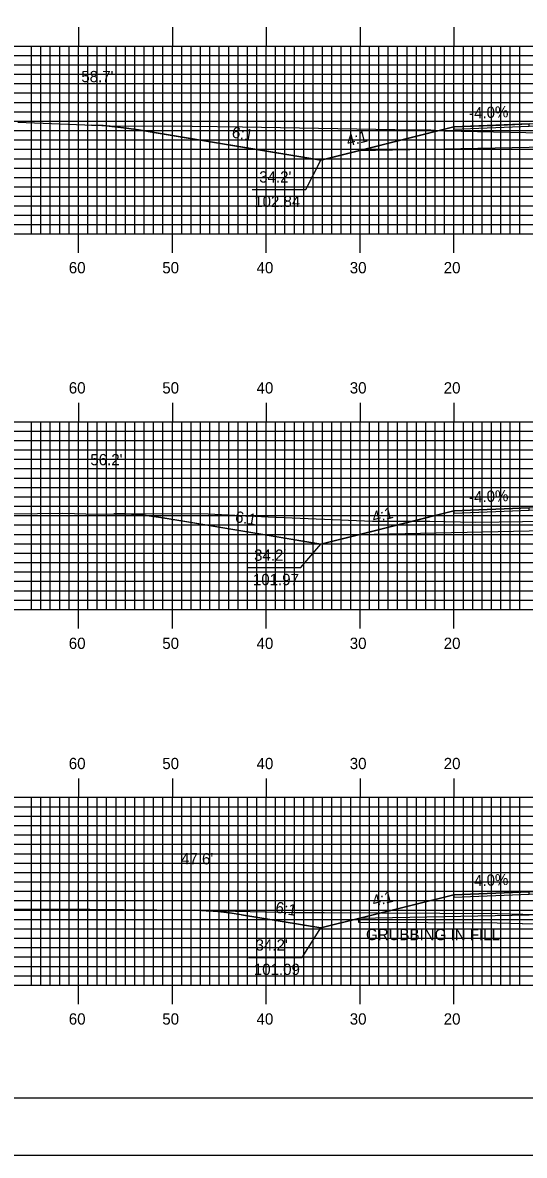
# Model space of a CAD drawing. Extents: x 1779106 to 1779449, y 442591 to 442811.
# Drawn here: x 1779205.4 to 1779258.8, y 442590.5 to 442711.2 of the extents above; entities that cross this region are included whole.
import ezdxf

# ---------------------------------------------------------------- set-up
doc = ezdxf.new("R2010")
doc.units = 0
for name, color, linetype in [('ANNOTATION', 7, 'Continuous'), ('BORDER', 7, 'Continuous'), ('D_Roadway_Centerline', 7, 'Continuous'), ('D_Roadway_Edge_Shoulder', 7, 'Continuous'), ('D_Roadway_SlopeLines', 7, 'Continuous'), ('D_Roadway_SubGrade', 7, 'Continuous'), ('D_Text_Standard', 7, 'Continuous'), ('GRUBBING IN FILL', 7, 'Continuous'), ('H_V ANNOTATION', 7, 'Continuous'), ('MAJOR', 7, 'Continuous'), ('MINOR', 7, 'Continuous'), ('PLOT BOUNDARY', 7, 'Continuous'), ('S_Roadway_Centerline', 7, 'Continuous')]:
    doc.layers.add(name, color=color, linetype=linetype)

msp = doc.modelspace()

# ---------------------------------------------------------------- linework, layer by layer
at = {"layer": 'ANNOTATION'}
for points in [[(1779229.85, 442693.4), (1779235.54, 442693.4), (1779237.16, 442696.51)], [(1779229.3, 442653.13), (1779235, 442653.13), (1779237.16, 442655.63)], [(1779229.46, 442611.62), (1779235.15, 442611.62), (1779237.16, 442614.76)]]:
    msp.add_lwpolyline(points, dxfattribs=at)
at = {"layer": 'BORDER'}
msp.add_lwpolyline([(1779121.73, 442596.67), (1779441.73, 442596.67), (1779441.73, 442806.67), (1779121.73, 442806.67)], close=True, dxfattribs=at)
at = {"layer": 'D_Roadway_Centerline'}
for points in [[(1779212.71, 442700.25), (1779213.96, 442700.19), (1779215.21, 442700.08), (1779216.46, 442699.94), (1779217.71, 442699.75), (1779219.39, 442699.47), (1779237.16, 442696.51), (1779237.6, 442696.62), (1779241.15, 442697.51), (1779251.33, 442700.05), (1779255.5, 442700.22), (1779259.33, 442700.37), (1779269.01, 442700.57), (1779271.33, 442700.61), (1779283.33, 442700.37), (1779289, 442700.15), (1779296.66, 442699.84), (1779306.37, 442697.41)], [(1779215.1, 442658.85), (1779216.35, 442658.84), (1779217.6, 442658.78), (1779217.76, 442658.76), (1779218.85, 442658.66), (1779220.1, 442658.48), (1779222.99, 442658), (1779237.16, 442655.63), (1779241.15, 442656.63), (1779251.33, 442659.18), (1779259.33, 442659.5), (1779271.33, 442659.74), (1779283.33, 442659.5), (1779300, 442658.83), (1779307.08, 442657.06), (1779309.41, 442656.48)], [(1779223.68, 442616.65), (1779224.43, 442616.61), (1779224.94, 442616.59), (1779225.68, 442616.54), (1779226.18, 442616.5), (1779227.43, 442616.36), (1779228.62, 442616.18), (1779228.69, 442616.17), (1779237.16, 442614.76), (1779241.16, 442615.76), (1779251.33, 442618.3), (1779259.33, 442618.62), (1779271.33, 442618.86), (1779271.33, 442618.86), (1779276.97, 442618.75), (1779283.33, 442618.62), (1779289.1, 442618.39), (1779303.33, 442617.82)]]:
    msp.add_lwpolyline(points, dxfattribs=at)
at = {"layer": 'D_Roadway_Edge_Shoulder'}
for points in [[(1779259.33, 442700.37), (1779251.33, 442700.05), (1779251.33, 442699.8), (1779259.33, 442700.12)], [(1779259.33, 442659.5), (1779251.33, 442659.18), (1779251.33, 442658.93), (1779259.33, 442659.25)], [(1779259.33, 442618.62), (1779251.33, 442618.3), (1779251.33, 442618.05), (1779259.33, 442618.37)]]:
    msp.add_lwpolyline(points, close=True, dxfattribs=at)
at = {"layer": 'D_Roadway_SlopeLines'}
for points in [[(1779237.16, 442696.51), (1779217.71, 442699.75), (1779216.46, 442699.94), (1779215.21, 442700.08), (1779213.96, 442700.19), (1779212.71, 442700.25)], [(1779251.33, 442700.05), (1779237.16, 442696.51)], [(1779237.16, 442655.63), (1779220.1, 442658.48), (1779218.85, 442658.66), (1779217.6, 442658.78), (1779216.35, 442658.84), (1779215.1, 442658.85)], [(1779251.33, 442659.18), (1779237.16, 442655.63)], [(1779251.33, 442618.3), (1779237.16, 442614.76)], [(1779237.16, 442614.76), (1779228.69, 442616.17), (1779227.43, 442616.36), (1779226.18, 442616.5), (1779224.94, 442616.59), (1779223.68, 442616.65)]]:
    msp.add_lwpolyline(points, dxfattribs=at)
at = {"layer": 'D_Roadway_SubGrade'}
for points in [[(1779259.33, 442697.87), (1779241.15, 442697.51), (1779251.33, 442700.05), (1779251.33, 442699.8), (1779259.33, 442700.12), (1779271.33, 442700.36), (1779283.33, 442700.12), (1779296.66, 442699.59), (1779296.66, 442699.84), (1779306.37, 442697.41), (1779283.33, 442697.87), (1779271.33, 442698.11)], [(1779259.33, 442657), (1779241.15, 442656.63), (1779251.33, 442659.18), (1779251.33, 442658.93), (1779259.33, 442659.25), (1779271.33, 442659.49), (1779283.33, 442659.25), (1779300, 442658.58), (1779300, 442658.83), (1779309.41, 442656.48), (1779283.33, 442657), (1779271.33, 442657.24)], [(1779259.33, 442616.12), (1779241.16, 442615.76), (1779251.33, 442618.3), (1779251.33, 442618.05), (1779259.33, 442618.37), (1779271.33, 442618.61), (1779283.33, 442618.37), (1779303.33, 442617.57), (1779303.33, 442617.82), (1779312.46, 442615.54), (1779283.33, 442616.12), (1779271.33, 442616.36)]]:
    msp.add_lwpolyline(points, close=True, dxfattribs=at)
at = {"layer": 'GRUBBING IN FILL'}
msp.add_line((1779241.16, 442615.76), (1779241.16, 442615.37), dxfattribs=at)
msp.add_line((1779241.16, 442615.76), (1779241.16, 442615.37), dxfattribs=at)
msp.add_lwpolyline([(1779241.16, 442615.76), (1779241.16, 442615.37), (1779248.55, 442615.34), (1779255.95, 442615.31), (1779259.9, 442615.21), (1779270.16, 442614.86), (1779271.33, 442614.86), (1779271.33, 442615.86), (1779270.18, 442615.86), (1779265.69, 442616.03), (1779261.74, 442616.17), (1779259.33, 442616.12), (1779250.24, 442615.94)], close=True, dxfattribs=at)
msp.add_lwpolyline([(1779241.16, 442615.76), (1779241.16, 442615.37), (1779248.55, 442615.34), (1779255.95, 442615.31), (1779259.9, 442615.21), (1779270.16, 442614.86), (1779271.33, 442614.86), (1779271.33, 442615.86), (1779270.18, 442615.86), (1779265.69, 442616.03), (1779261.74, 442616.17), (1779259.33, 442616.12), (1779250.24, 442615.94)], close=True, dxfattribs=at)
msp.add_lwpolyline([(1779241.16, 442615.37), (1779255.95, 442615.31), (1779258.64, 442615.23), (1779261.17, 442615.19), (1779270.16, 442614.86), (1779280.39, 442614.79), (1779284.94, 442614.75), (1779301.5, 442614.5)], dxfattribs=at)
msp.add_lwpolyline([(1779241.16, 442615.37), (1779255.95, 442615.31), (1779258.64, 442615.23), (1779261.17, 442615.19), (1779270.16, 442614.86), (1779280.39, 442614.79), (1779284.94, 442614.75), (1779301.5, 442614.5)], dxfattribs=at)
at = {"layer": 'MAJOR'}
for p, q in [((1779211.33, 442710.67), (1779211.33, 442708.67)), ((1779221.33, 442710.67), (1779221.33, 442708.67)), ((1779231.33, 442710.67), (1779231.33, 442708.67)), ((1779241.33, 442710.67), (1779241.33, 442708.67)), ((1779251.33, 442710.67), (1779251.33, 442708.67)), ((1779131.33, 442708.67), (1779411.33, 442708.67)), ((1779131.33, 442708.67), (1779411.33, 442708.67)), ((1779211.33, 442688.67), (1779211.33, 442708.67)), ((1779221.33, 442688.67), (1779221.33, 442708.67)), ((1779231.33, 442688.67), (1779231.33, 442708.67)), ((1779241.33, 442688.67), (1779241.33, 442708.67)), ((1779251.33, 442688.67), (1779251.33, 442708.67)), ((1779131.33, 442703.67), (1779411.33, 442703.67)), ((1779131.96, 442698.67), (1779411.96, 442698.67)), ((1779131.33, 442693.67), (1779411.33, 442693.67)), ((1779131.33, 442688.67), (1779411.33, 442688.67)), ((1779131.33, 442688.67), (1779411.33, 442688.67)), ((1779211.33, 442686.66), (1779211.33, 442688.67)), ((1779221.33, 442686.66), (1779221.33, 442688.67)), ((1779231.33, 442686.66), (1779231.33, 442688.67)), ((1779241.33, 442686.66), (1779241.33, 442688.67)), ((1779251.33, 442686.66), (1779251.33, 442688.67)), ((1779211.33, 442670.67), (1779211.33, 442668.67)), ((1779221.33, 442670.67), (1779221.33, 442668.67)), ((1779231.33, 442670.67), (1779231.33, 442668.67)), ((1779241.33, 442670.67), (1779241.33, 442668.67)), ((1779251.33, 442670.67), (1779251.33, 442668.67)), ((1779131.33, 442668.67), (1779411.33, 442668.67)), ((1779131.33, 442668.67), (1779411.33, 442668.67)), ((1779211.33, 442648.67), (1779211.33, 442668.67)), ((1779221.33, 442648.67), (1779221.33, 442668.67)), ((1779231.33, 442648.67), (1779231.33, 442668.67)), ((1779241.33, 442648.67), (1779241.33, 442668.67)), ((1779251.33, 442648.67), (1779251.33, 442668.67)), ((1779131.33, 442663.67), (1779411.33, 442663.67)), ((1779131.33, 442658.67), (1779411.33, 442658.67)), ((1779131.33, 442653.67), (1779411.33, 442653.67)), ((1779131.33, 442648.67), (1779411.33, 442648.67)), ((1779131.33, 442648.67), (1779411.33, 442648.67)), ((1779211.33, 442646.66), (1779211.33, 442648.67)), ((1779221.33, 442646.66), (1779221.33, 442648.67)), ((1779231.33, 442646.66), (1779231.33, 442648.67)), ((1779241.33, 442646.66), (1779241.33, 442648.67)), ((1779251.33, 442646.66), (1779251.33, 442648.67)), ((1779211.33, 442630.67), (1779211.33, 442628.67)), ((1779221.33, 442630.67), (1779221.33, 442628.67)), ((1779231.33, 442630.67), (1779231.33, 442628.67)), ((1779241.33, 442630.67), (1779241.33, 442628.67)), ((1779251.33, 442630.67), (1779251.33, 442628.67)), ((1779131.33, 442628.67), (1779411.33, 442628.67)), ((1779131.33, 442628.67), (1779411.33, 442628.67)), ((1779211.33, 442608.67), (1779211.33, 442628.67)), ((1779221.33, 442608.67), (1779221.33, 442628.67)), ((1779231.33, 442608.67), (1779231.33, 442628.67)), ((1779241.33, 442608.67), (1779241.33, 442628.67)), ((1779251.33, 442608.67), (1779251.33, 442628.67)), ((1779131.33, 442623.67), (1779411.33, 442623.67)), ((1779131.33, 442618.67), (1779411.33, 442618.67)), ((1779131.33, 442613.67), (1779411.33, 442613.67)), ((1779131.33, 442608.67), (1779411.33, 442608.67)), ((1779131.33, 442608.67), (1779411.33, 442608.67)), ((1779211.33, 442606.66), (1779211.33, 442608.67)), ((1779221.33, 442606.66), (1779221.33, 442608.67)), ((1779231.33, 442606.66), (1779231.33, 442608.67)), ((1779241.33, 442606.66), (1779241.33, 442608.67)), ((1779251.33, 442606.66), (1779251.33, 442608.67))]:
    msp.add_line(p, q, dxfattribs=at)
at = {"layer": 'MINOR'}
for p, q in [((1779206.33, 442688.67), (1779206.33, 442708.67)), ((1779207.33, 442688.67), (1779207.33, 442708.67)), ((1779208.33, 442688.67), (1779208.33, 442708.67)), ((1779209.33, 442688.67), (1779209.33, 442708.67)), ((1779210.33, 442688.67), (1779210.33, 442708.67)), ((1779212.33, 442688.67), (1779212.33, 442708.67)), ((1779213.33, 442688.67), (1779213.33, 442708.67)), ((1779214.33, 442688.67), (1779214.33, 442708.67)), ((1779215.33, 442688.67), (1779215.33, 442708.67)), ((1779216.33, 442688.67), (1779216.33, 442708.67)), ((1779217.33, 442688.67), (1779217.33, 442708.67)), ((1779218.33, 442688.67), (1779218.33, 442708.67)), ((1779219.33, 442688.67), (1779219.33, 442708.67)), ((1779220.33, 442688.67), (1779220.33, 442708.67)), ((1779222.33, 442688.67), (1779222.33, 442708.67)), ((1779223.33, 442688.67), (1779223.33, 442708.67)), ((1779224.33, 442688.67), (1779224.33, 442708.67)), ((1779225.33, 442688.67), (1779225.33, 442708.67)), ((1779226.33, 442688.67), (1779226.33, 442708.67)), ((1779227.33, 442688.67), (1779227.33, 442708.67)), ((1779228.33, 442688.67), (1779228.33, 442708.67)), ((1779229.33, 442688.67), (1779229.33, 442708.67)), ((1779230.33, 442688.67), (1779230.33, 442708.67)), ((1779232.33, 442688.67), (1779232.33, 442708.67)), ((1779233.33, 442688.67), (1779233.33, 442708.67)), ((1779234.33, 442688.67), (1779234.33, 442708.67)), ((1779235.33, 442688.67), (1779235.33, 442708.67)), ((1779236.33, 442688.67), (1779236.33, 442708.67)), ((1779237.33, 442688.67), (1779237.33, 442708.67)), ((1779238.33, 442688.67), (1779238.33, 442708.67)), ((1779239.33, 442688.67), (1779239.33, 442708.67)), ((1779240.33, 442688.67), (1779240.33, 442708.67)), ((1779242.33, 442688.67), (1779242.33, 442708.67)), ((1779243.33, 442688.67), (1779243.33, 442708.67)), ((1779244.33, 442688.67), (1779244.33, 442708.67)), ((1779245.33, 442688.67), (1779245.33, 442708.67)), ((1779246.33, 442688.67), (1779246.33, 442708.67)), ((1779247.33, 442688.67), (1779247.33, 442708.67)), ((1779248.33, 442688.67), (1779248.33, 442708.67)), ((1779249.33, 442688.67), (1779249.33, 442708.67)), ((1779250.33, 442688.67), (1779250.33, 442708.67)), ((1779252.33, 442688.67), (1779252.33, 442708.67)), ((1779253.33, 442688.67), (1779253.33, 442708.67)), ((1779254.33, 442688.67), (1779254.33, 442708.67)), ((1779255.33, 442688.67), (1779255.33, 442708.67)), ((1779256.33, 442688.67), (1779256.33, 442708.67)), ((1779257.33, 442688.67), (1779257.33, 442708.67)), ((1779258.33, 442688.67), (1779258.33, 442708.67)), ((1779131.33, 442707.67), (1779411.33, 442707.67)), ((1779131.33, 442706.67), (1779411.33, 442706.67)), ((1779131.33, 442705.67), (1779411.33, 442705.67)), ((1779131.33, 442704.67), (1779411.33, 442704.67)), ((1779131.33, 442702.67), (1779411.33, 442702.67)), ((1779131.33, 442701.67), (1779411.33, 442701.67)), ((1779131.33, 442700.67), (1779411.33, 442700.67)), ((1779131.33, 442699.67), (1779411.33, 442699.67)), ((1779131.33, 442697.67), (1779411.33, 442697.67)), ((1779131.33, 442696.67), (1779411.33, 442696.67)), ((1779131.33, 442695.67), (1779411.33, 442695.67)), ((1779131.33, 442694.67), (1779411.33, 442694.67)), ((1779131.33, 442692.67), (1779411.33, 442692.67)), ((1779131.33, 442691.67), (1779411.33, 442691.67)), ((1779131.33, 442690.67), (1779411.33, 442690.67)), ((1779131.33, 442689.67), (1779411.33, 442689.67)), ((1779206.33, 442648.67), (1779206.33, 442668.67)), ((1779207.33, 442648.67), (1779207.33, 442668.67)), ((1779208.33, 442648.67), (1779208.33, 442668.67)), ((1779209.33, 442648.67), (1779209.33, 442668.67)), ((1779210.33, 442648.67), (1779210.33, 442668.67)), ((1779212.33, 442648.67), (1779212.33, 442668.67)), ((1779213.33, 442648.67), (1779213.33, 442668.67)), ((1779214.33, 442648.67), (1779214.33, 442668.67)), ((1779215.33, 442648.67), (1779215.33, 442668.67)), ((1779216.33, 442648.67), (1779216.33, 442668.67)), ((1779217.33, 442648.67), (1779217.33, 442668.67)), ((1779218.33, 442648.67), (1779218.33, 442668.67)), ((1779219.33, 442648.67), (1779219.33, 442668.67)), ((1779220.33, 442648.67), (1779220.33, 442668.67)), ((1779222.33, 442648.67), (1779222.33, 442668.67)), ((1779223.33, 442648.67), (1779223.33, 442668.67)), ((1779224.33, 442648.67), (1779224.33, 442668.67)), ((1779225.33, 442648.67), (1779225.33, 442668.67)), ((1779226.33, 442648.67), (1779226.33, 442668.67)), ((1779227.33, 442648.67), (1779227.33, 442668.67)), ((1779228.33, 442648.67), (1779228.33, 442668.67)), ((1779229.33, 442648.67), (1779229.33, 442668.67)), ((1779230.33, 442648.67), (1779230.33, 442668.67)), ((1779232.33, 442648.67), (1779232.33, 442668.67)), ((1779233.33, 442648.67), (1779233.33, 442668.67)), ((1779234.33, 442648.67), (1779234.33, 442668.67)), ((1779235.33, 442648.67), (1779235.33, 442668.67)), ((1779236.33, 442648.67), (1779236.33, 442668.67)), ((1779237.33, 442648.67), (1779237.33, 442668.67)), ((1779238.33, 442648.67), (1779238.33, 442668.67)), ((1779239.33, 442648.67), (1779239.33, 442668.67)), ((1779240.33, 442648.67), (1779240.33, 442668.67)), ((1779242.33, 442648.67), (1779242.33, 442668.67)), ((1779243.33, 442648.67), (1779243.33, 442668.67)), ((1779244.33, 442648.67), (1779244.33, 442668.67)), ((1779245.33, 442648.67), (1779245.33, 442668.67)), ((1779246.33, 442648.67), (1779246.33, 442668.67)), ((1779247.33, 442648.67), (1779247.33, 442668.67)), ((1779248.33, 442648.67), (1779248.33, 442668.67)), ((1779249.33, 442648.67), (1779249.33, 442668.67)), ((1779250.33, 442648.67), (1779250.33, 442668.67)), ((1779252.33, 442648.67), (1779252.33, 442668.67)), ((1779253.33, 442648.67), (1779253.33, 442668.67)), ((1779254.33, 442648.67), (1779254.33, 442668.67)), ((1779255.33, 442648.67), (1779255.33, 442668.67)), ((1779256.33, 442648.67), (1779256.33, 442668.67)), ((1779257.33, 442648.67), (1779257.33, 442668.67)), ((1779258.33, 442648.67), (1779258.33, 442668.67)), ((1779131.33, 442667.67), (1779411.33, 442667.67)), ((1779131.33, 442666.67), (1779411.33, 442666.67)), ((1779131.33, 442665.67), (1779411.33, 442665.67)), ((1779131.33, 442664.67), (1779411.33, 442664.67)), ((1779131.33, 442662.67), (1779411.33, 442662.67)), ((1779131.33, 442661.67), (1779411.33, 442661.67)), ((1779131.33, 442660.67), (1779411.33, 442660.67)), ((1779131.33, 442659.67), (1779411.33, 442659.67)), ((1779131.33, 442657.67), (1779411.33, 442657.67)), ((1779131.33, 442656.67), (1779411.33, 442656.67)), ((1779131.33, 442655.67), (1779411.33, 442655.67)), ((1779131.33, 442654.67), (1779411.33, 442654.67)), ((1779131.33, 442652.67), (1779411.33, 442652.67)), ((1779131.33, 442651.67), (1779411.33, 442651.67)), ((1779131.33, 442650.67), (1779411.33, 442650.67)), ((1779131.33, 442649.67), (1779411.33, 442649.67)), ((1779206.33, 442608.67), (1779206.33, 442628.67)), ((1779207.33, 442608.67), (1779207.33, 442628.67)), ((1779208.33, 442608.67), (1779208.33, 442628.67)), ((1779209.33, 442608.67), (1779209.33, 442628.67)), ((1779210.33, 442608.67), (1779210.33, 442628.67)), ((1779212.33, 442608.67), (1779212.33, 442628.67)), ((1779213.33, 442608.67), (1779213.33, 442628.67)), ((1779214.33, 442608.67), (1779214.33, 442628.67)), ((1779215.33, 442608.67), (1779215.33, 442628.67)), ((1779216.33, 442608.67), (1779216.33, 442628.67)), ((1779217.33, 442608.67), (1779217.33, 442628.67)), ((1779218.33, 442608.67), (1779218.33, 442628.67)), ((1779219.33, 442608.67), (1779219.33, 442628.67)), ((1779220.33, 442608.67), (1779220.33, 442628.67)), ((1779222.33, 442608.67), (1779222.33, 442628.67)), ((1779223.33, 442608.67), (1779223.33, 442628.67)), ((1779224.33, 442608.67), (1779224.33, 442628.67)), ((1779225.33, 442608.67), (1779225.33, 442628.67)), ((1779226.33, 442608.67), (1779226.33, 442628.67)), ((1779227.33, 442608.67), (1779227.33, 442628.67)), ((1779228.33, 442608.67), (1779228.33, 442628.67)), ((1779229.33, 442608.67), (1779229.33, 442628.67)), ((1779230.33, 442608.67), (1779230.33, 442628.67)), ((1779232.33, 442608.67), (1779232.33, 442628.67)), ((1779233.33, 442608.67), (1779233.33, 442628.67)), ((1779234.33, 442608.67), (1779234.33, 442628.67)), ((1779235.33, 442608.67), (1779235.33, 442628.67)), ((1779236.33, 442608.67), (1779236.33, 442628.67)), ((1779237.33, 442608.67), (1779237.33, 442628.67)), ((1779238.33, 442608.67), (1779238.33, 442628.67)), ((1779239.33, 442608.67), (1779239.33, 442628.67)), ((1779240.33, 442608.67), (1779240.33, 442628.67)), ((1779242.33, 442608.67), (1779242.33, 442628.67)), ((1779243.33, 442608.67), (1779243.33, 442628.67)), ((1779244.33, 442608.67), (1779244.33, 442628.67)), ((1779245.33, 442608.67), (1779245.33, 442628.67)), ((1779246.33, 442608.67), (1779246.33, 442628.67)), ((1779247.33, 442608.67), (1779247.33, 442628.67)), ((1779248.33, 442608.67), (1779248.33, 442628.67)), ((1779249.33, 442608.67), (1779249.33, 442628.67)), ((1779250.33, 442608.67), (1779250.33, 442628.67)), ((1779252.33, 442608.67), (1779252.33, 442628.67)), ((1779253.33, 442608.67), (1779253.33, 442628.67)), ((1779254.33, 442608.67), (1779254.33, 442628.67)), ((1779255.33, 442608.67), (1779255.33, 442628.67)), ((1779256.33, 442608.67), (1779256.33, 442628.67)), ((1779257.33, 442608.67), (1779257.33, 442628.67)), ((1779258.33, 442608.67), (1779258.33, 442628.67)), ((1779131.33, 442627.67), (1779411.33, 442627.67)), ((1779131.33, 442626.67), (1779411.33, 442626.67)), ((1779131.33, 442625.67), (1779411.33, 442625.67)), ((1779131.33, 442624.67), (1779411.33, 442624.67)), ((1779131.33, 442622.67), (1779411.33, 442622.67)), ((1779131.33, 442621.67), (1779411.33, 442621.67)), ((1779131.33, 442620.67), (1779411.33, 442620.67)), ((1779131.33, 442619.67), (1779411.33, 442619.67)), ((1779131.33, 442617.67), (1779411.33, 442617.67)), ((1779131.33, 442616.67), (1779411.33, 442616.67)), ((1779131.33, 442615.67), (1779411.33, 442615.67)), ((1779131.33, 442614.67), (1779411.33, 442614.67)), ((1779131.33, 442612.67), (1779411.33, 442612.67)), ((1779131.33, 442611.67), (1779411.33, 442611.67)), ((1779131.33, 442610.67), (1779411.33, 442610.67)), ((1779131.33, 442609.67), (1779411.33, 442609.67))]:
    msp.add_line(p, q, dxfattribs=at)
at = {"layer": 'PLOT BOUNDARY'}
msp.add_lwpolyline([(1779105.54, 442590.55), (1779445.54, 442590.55), (1779445.54, 442810.55), (1779105.54, 442810.55)], close=True, dxfattribs=at)
at = {"layer": 'S_Roadway_Centerline'}
for points in [[(1779204.87, 442700.58), (1779214.72, 442700.17), (1779223.43, 442700.12), (1779228.79, 442700.06), (1779247.05, 442699.73), (1779248.88, 442699.73), (1779250.39, 442699.65), (1779269.31, 442699.25), (1779271.55, 442699.27), (1779274.07, 442699.29), (1779294.37, 442699.04), (1779296.51, 442699), (1779318.54, 442698.62), (1779319.86, 442698.59), (1779340.93, 442698.43)], [(1779190.73, 442658.67), (1779209.66, 442658.92), (1779213.36, 442658.82), (1779217.3, 442658.89), (1779225.14, 442658.87), (1779231.55, 442658.53), (1779242.66, 442658.06), (1779248.77, 442658.06), (1779253.67, 442657.98), (1779266.04, 442658.15), (1779271.43, 442658.22), (1779276.63, 442657.93), (1779282.72, 442657.53), (1779289.37, 442657.51), (1779305.66, 442657.76), (1779313.39, 442657.81), (1779317.15, 442657.71), (1779321.52, 442657.67), (1779341.31, 442657.13)], [(1779192.27, 442616.68), (1779209.36, 442616.78), (1779212.55, 442616.76), (1779223.26, 442616.65), (1779234.43, 442616.4), (1779237.51, 442616.39), (1779255.96, 442616.31), (1779258.66, 442616.23), (1779261.19, 442616.19), (1779270.18, 442615.86), (1779280.4, 442615.79), (1779284.96, 442615.75), (1779302.19, 442615.49), (1779305.57, 442615.39), (1779308.79, 442615.46), (1779323.54, 442615.33), (1779327.98, 442615.12), (1779346.56, 442615.33)]]:
    msp.add_lwpolyline(points, dxfattribs=at)

# ---------------------------------------------------------------- texts
at = {"layer": 'ANNOTATION'}
for s, rotation, p in [('-4.0%', 2.2907, (1779252.96, 442700.92)), ('6:1', 350.5379, (1779227.61, 442698.93)), ('4:1', 14.0339, (1779240.04, 442697.98)), ('-4.0%', 2.2905, (1779252.96, 442660.04)), ('6:1', 350.5373, (1779227.96, 442657.99)), ('4:1', 14.034, (1779242.78, 442657.9)), ('-4.0%', 2.2905, (1779252.96, 442619.17)), ('6:1', 350.5354, (1779232.25, 442616.4)), ('4:1', 14.0347, (1779242.78, 442617.03))]:
    msp.add_text(s, height=1.2, rotation=rotation, dxfattribs=at).set_placement(p)
for s, p in [("34.2'", (1779230.58, 442694.13)), ('102.84', (1779230.05, 442691.53)), ("34.2'", (1779230.04, 442653.86)), ('101.97', (1779229.91, 442651.26)), ("34.2'", (1779230.2, 442612.35)), ('101.09', (1779230.01, 442609.75))]:
    msp.add_text(s, height=1.2, dxfattribs=at).set_placement(p)
at = {"layer": 'D_Text_Standard'}
for s, p in [("58.7'", (1779211.63, 442704.82)), ("56.2'", (1779212.59, 442664.03)), ("47.6'", (1779222.26, 442621.53))]:
    msp.add_text(s, height=1.2, dxfattribs=at).set_placement(p)
at = {"layer": 'GRUBBING IN FILL'}
msp.add_text('GRUBBING IN FILL', height=1.2, rotation=359.9351, dxfattribs=at).set_placement((1779241.96, 442613.46))
at = {"layer": 'H_V ANNOTATION'}
for s, p in [('60', (1779210.3, 442684.47)), ('50', (1779220.26, 442684.47)), ('40', (1779230.3, 442684.47)), ('30', (1779240.23, 442684.47)), ('20', (1779250.24, 442684.47)), ('60', (1779210.3, 442671.67)), ('50', (1779220.26, 442671.67)), ('40', (1779230.3, 442671.67)), ('30', (1779240.23, 442671.67)), ('20', (1779250.24, 442671.67)), ('60', (1779210.3, 442644.47)), ('50', (1779220.26, 442644.47)), ('40', (1779230.3, 442644.47)), ('30', (1779240.23, 442644.47)), ('20', (1779250.24, 442644.47)), ('60', (1779210.3, 442631.67)), ('50', (1779220.26, 442631.67)), ('40', (1779230.3, 442631.67)), ('30', (1779240.23, 442631.67)), ('20', (1779250.24, 442631.67)), ('60', (1779210.3, 442604.47)), ('50', (1779220.26, 442604.47)), ('40', (1779230.3, 442604.47)), ('30', (1779240.23, 442604.47)), ('20', (1779250.24, 442604.47))]:
    msp.add_text(s, height=1.2, dxfattribs=at).set_placement(p)

doc.saveas('drawing.dxf')
